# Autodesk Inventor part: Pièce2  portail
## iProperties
Shininess: 20.0
Angle Display Precision: 2
Document Length Units: 11269
Document Angle Units: 11279
Document Time Units: 11290
Document Mass Units: 11283
Document Length Units Precision: 3
Document Angle Units Precision: 2
Compacted: True
Created: 2009-07
Part Number: Pièce2  portail
Material: Par défaut
Document SubType Name: Modélisation
Designer: EL
Density: 1 g/cm^3
Density: 0.0
Volumn: 0.0
Area: 0.0
PropertySet Name: Model Information
Control State: 0
Master: False
Checked Out: False
Author: EL
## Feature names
1. Extrusion1
2. Extrusion2
3. Extrusion3
4. Extrusion4
5. Extrusion5
6. Extrusion6
7. Extrusion7
8. Extrusion8
9. Extrusion9
